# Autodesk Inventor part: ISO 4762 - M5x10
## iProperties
Created: 2001-09
Part Number: ISO 4762 - M5x10
Catalog Web Link: file:///D:/Program%20Files/Autodesk/Inventor%205/Content/Iso/index.htm?doNavigateId=932883F9-F3A7-4770-8571-ED868C9DA26C|BD6CAEC25FC54C5988A91C985F78BFEA|true
Description: Hexagon Socket Head Cap Screw
Document SubType Name: Standard Catalog Part
Standard: ISO 4762 - M5x10
Designer: Martin Budgell
Control State: 0
Master: False
Checked Out: False
Shininess: 64.0
Angle Display Precision: 2
Document Length Units: 11269
Document Angle Units: 11279
Document Time Units: 11290
Document Mass Units: 11283
Document Length Units Precision: 3
Document Angle Units Precision: 2
Compacted: True
CLASSIFICATION: 31161501 un/spsc
MANUFACTURER: ISO Standard System
Density: 0.0
Volumn: 0.0
Area: 0.0
PropertySet Name: Model Information
Author: Martin Budgell
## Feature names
1. Base1
